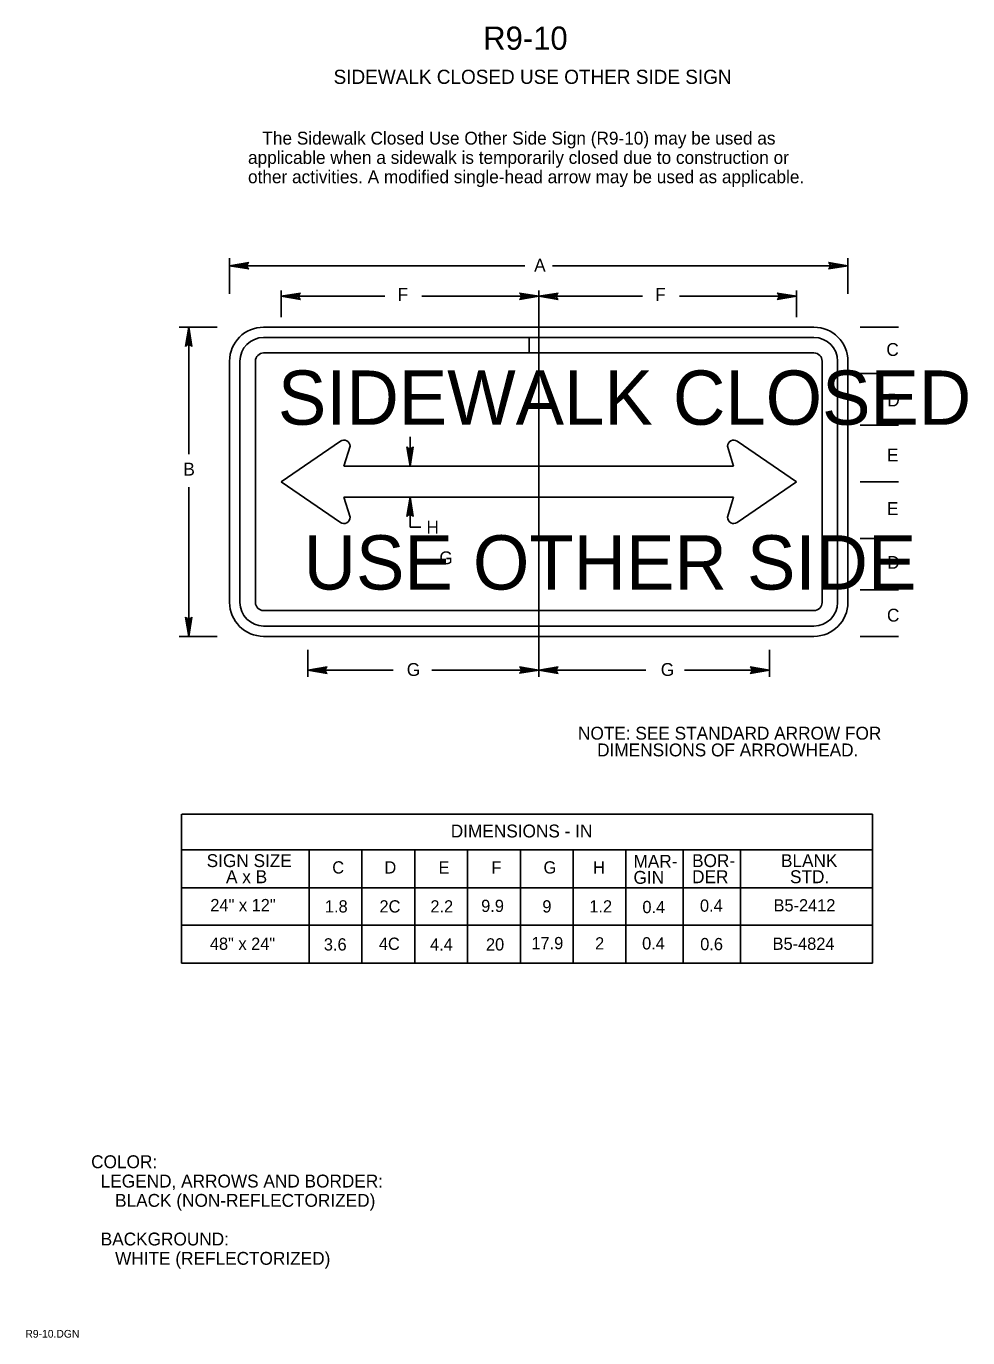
# Model space of a CAD drawing. Extents: x 0.013 to 0.195, y 0.005 to 0.259.
import ezdxf

# ---------------------------------------------------------------- set-up
doc = ezdxf.new("R2010")
doc.units = 0
for name, color, linetype in [('1', 7, 'Continuous'), ('2', 7, 'Continuous'), ('3', 7, 'Continuous')]:
    doc.layers.add(name, color=color, linetype=linetype)

# ---------------------------------------------------------------- blocks, each defined once
blk = doc.blocks.new('RARROW')
at = {"layer": '3'}
for p, q in [((-2.156, 0.28500000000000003), (-2.2665, 0.384625)), ((-2.2665, 0.384625), (0, 0)), ((0, 0), (-2.2665, -0.379125)), ((-2.156, 0.28500000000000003), (-2.075625, 0.12075)), ((0, 0), (-2.156, 0.28500000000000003)), ((-2.14975, -0.2705), (0, 0)), ((-2.075625, 0.12075), (0, 0)), ((0, 0), (-2.074, -0.108)), ((-2.2665, -0.379125), (-2.14975, -0.2705)), ((-2.074, -0.108), (-2.14975, -0.2705))]:
    blk.add_line(p, q, dxfattribs=at)

msp = doc.modelspace()

# ---------------------------------------------------------------- linework, layer by layer
at = {"layer": '1'}
for p, q in [((0.06199842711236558, 0.20792631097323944), (0.06199842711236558, 0.20273818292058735)), ((0.11199842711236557, 0.20792631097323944), (0.11199842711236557, 0.20273818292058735)), ((0.16199842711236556, 0.20792631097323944), (0.16199842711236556, 0.20273818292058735)), ((0.11199842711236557, 0.20504784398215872), (0.11199842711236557, 0.1329625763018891)), ((0.04960895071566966, 0.20079298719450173), (0.04220895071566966, 0.20079298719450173)), ((0.05859842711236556, 0.19879298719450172), (0.11011711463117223, 0.19879298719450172)), ((0.11011711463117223, 0.19879298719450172), (0.11011711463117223, 0.19579298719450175)), ((0.11011711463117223, 0.19579298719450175), (0.11011711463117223, 0.19879298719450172)), ((0.11011711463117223, 0.19879298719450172), (0.1653984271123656, 0.19879298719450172)), ((0.17438790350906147, 0.20079298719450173), (0.1817879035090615, 0.20079298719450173)), ((0.05399842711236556, 0.1473929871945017), (0.05399842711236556, 0.1941929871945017)), ((0.05699842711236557, 0.1941929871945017), (0.05699842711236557, 0.1473929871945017)), ((0.11011711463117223, 0.19579298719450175), (0.05859842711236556, 0.19579298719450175)), ((0.1653984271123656, 0.19579298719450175), (0.11011711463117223, 0.19579298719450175)), ((0.16699842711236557, 0.1473929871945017), (0.16699842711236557, 0.1941929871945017)), ((0.16999842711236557, 0.1941929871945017), (0.16999842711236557, 0.1473929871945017)), ((0.17438790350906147, 0.19179298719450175), (0.1817879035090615, 0.19179298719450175)), ((0.17438790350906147, 0.18179298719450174), (0.1817879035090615, 0.18179298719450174)), ((0.07349961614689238, 0.17868254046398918), (0.06199842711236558, 0.17079298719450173)), ((0.16199842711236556, 0.1707929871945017), (0.15049723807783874, 0.17868254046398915)), ((0.07417451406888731, 0.17379298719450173), (0.07537842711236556, 0.17769298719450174)), ((0.14861842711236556, 0.17769298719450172), (0.14982234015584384, 0.1737929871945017)), ((0.1498223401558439, 0.17379298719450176), (0.07417451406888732, 0.17379298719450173)), ((0.06199842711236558, 0.17079298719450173), (0.07349961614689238, 0.16290343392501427)), ((0.15049723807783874, 0.16290343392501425), (0.16199842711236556, 0.1707929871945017)), ((0.17438790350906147, 0.17079298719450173), (0.1817879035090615, 0.17079298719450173)), ((0.07537842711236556, 0.16389298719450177), (0.07417451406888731, 0.16779298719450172)), ((0.07417451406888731, 0.16779298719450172), (0.1498223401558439, 0.16779298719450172)), ((0.14982234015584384, 0.1677929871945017), (0.14861842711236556, 0.16389298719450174)), ((0.0890998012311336, 0.1619828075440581), (0.08701613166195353, 0.1619828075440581)), ((0.17438790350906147, 0.15979298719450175), (0.1817879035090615, 0.15979298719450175)), ((0.17438790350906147, 0.14979298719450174), (0.1817879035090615, 0.14979298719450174)), ((0.05859842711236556, 0.14579298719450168), (0.1653984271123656, 0.14579298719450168)), ((0.1653984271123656, 0.14279298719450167), (0.05859842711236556, 0.14279298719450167)), ((0.04960895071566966, 0.14079298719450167), (0.04220895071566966, 0.14079298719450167)), ((0.17438790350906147, 0.14079298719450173), (0.1817879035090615, 0.14079298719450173)), ((0.06719842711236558, 0.1329625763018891), (0.06719842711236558, 0.1381507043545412)), ((0.11199842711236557, 0.1329625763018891), (0.11199842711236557, 0.1381507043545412)), ((0.15679842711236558, 0.1329625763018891), (0.15679842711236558, 0.1381507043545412))]:
    msp.add_line(p, q, dxfattribs=at)
for centre, radius, start, end in [((0.05859842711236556, 0.1941929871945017), 0.006600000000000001, 90, 180), ((0.05859842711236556, 0.1941929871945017), 0.004600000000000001, 90, 180), ((0.1653984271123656, 0.1941929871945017), 0.006600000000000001, 0, 90), ((0.1653984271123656, 0.1941929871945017), 0.004600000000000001, 0, 90), ((0.05859842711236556, 0.1941929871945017), 0.0016, 90, 180), ((0.1653984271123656, 0.1941929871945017), 0.0016, 0, 90), ((0.07417842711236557, 0.17769298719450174), 0.0012000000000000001, 0, 124.4492335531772), ((0.1498184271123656, 0.17769298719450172), 0.0012000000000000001, 55.550766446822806, 180), ((0.07417842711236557, 0.16389298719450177), 0.0012000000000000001, 235.55076644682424, 0), ((0.1498184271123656, 0.16389298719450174), 0.0012000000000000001, 180, 304.44923355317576), ((0.05859842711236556, 0.1473929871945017), 0.006600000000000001, 180, 270), ((0.05859842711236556, 0.1473929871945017), 0.004600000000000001, 180, 270), ((0.05859842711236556, 0.1473929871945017), 0.0016, 180, 270), ((0.1653984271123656, 0.1473929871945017), 0.006600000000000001, 270, 0), ((0.1653984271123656, 0.1473929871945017), 0.0016, 270, 0), ((0.1653984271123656, 0.1473929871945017), 0.004600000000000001, 270, 0)]:
    msp.add_arc(centre, radius, start, end, dxfattribs=at)
at = {"layer": '3'}
for p, q in [((0.05199842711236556, 0.2072463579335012), (0.05199842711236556, 0.21415649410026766)), ((0.17199842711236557, 0.2072463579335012), (0.17199842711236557, 0.21415649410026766)), ((0.10927705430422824, 0.21271933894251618), (0.05199842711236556, 0.21271933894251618)), ((0.11463473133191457, 0.21271933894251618), (0.17199842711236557, 0.21271933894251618)), ((0.08215111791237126, 0.2067858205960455), (0.06199842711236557, 0.2067858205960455)), ((0.11199842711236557, 0.2067858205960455), (0.08933127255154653, 0.2067858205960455)), ((0.13215111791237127, 0.2067858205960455), (0.11199842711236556, 0.2067858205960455)), ((0.16199842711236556, 0.2067858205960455), (0.13933127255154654, 0.2067858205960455)), ((0.044054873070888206, 0.17614255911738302), (0.044054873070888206, 0.20079298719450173)), ((0.05859842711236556, 0.20079298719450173), (0.1653984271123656, 0.20079298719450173)), ((0.05199842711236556, 0.1473929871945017), (0.05199842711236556, 0.1941929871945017)), ((0.17199842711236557, 0.1473929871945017), (0.17199842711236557, 0.1941929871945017)), ((0.08701613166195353, 0.17379298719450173), (0.08701613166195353, 0.1794839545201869)), ((0.044054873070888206, 0.14079298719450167), (0.044054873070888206, 0.1697685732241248)), ((0.08701613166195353, 0.1619828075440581), (0.08701613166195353, 0.16779298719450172)), ((0.05859842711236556, 0.14079298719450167), (0.1653984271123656, 0.14079298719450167)), ((0.08373753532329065, 0.13424514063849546), (0.06719842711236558, 0.13424514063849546)), ((0.11199842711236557, 0.13424514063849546), (0.09122230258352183, 0.13424514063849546)), ((0.11199842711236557, 0.13424514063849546), (0.13277455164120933, 0.13424514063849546)), ((0.1402593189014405, 0.13424514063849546), (0.15679842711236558, 0.13424514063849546)), ((0.042671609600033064, 0.10626767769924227), (0.042671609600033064, 0.07739267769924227)), ((0.04271319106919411, 0.10626480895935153), (0.1767966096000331, 0.10626480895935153)), ((0.1767966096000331, 0.10626767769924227), (0.1767966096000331, 0.07739554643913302)), ((0.1767966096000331, 0.09939267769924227), (0.042671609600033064, 0.09939267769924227)), ((0.06746319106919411, 0.09938980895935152), (0.06746319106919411, 0.07739267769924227)), ((0.07767160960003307, 0.09939267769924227), (0.07767160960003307, 0.07739267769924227)), ((0.08792160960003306, 0.09939267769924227), (0.08792160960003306, 0.07739267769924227)), ((0.09817160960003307, 0.09939267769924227), (0.09817160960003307, 0.07739267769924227)), ((0.10842160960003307, 0.09939267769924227), (0.10842160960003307, 0.07739267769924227)), ((0.11867160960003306, 0.09939267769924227), (0.11867160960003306, 0.07739267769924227)), ((0.12888002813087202, 0.09939554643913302), (0.12888002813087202, 0.07739554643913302)), ((0.1400466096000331, 0.09939267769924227), (0.1400466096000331, 0.07739554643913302)), ((0.1511716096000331, 0.09939267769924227), (0.1511716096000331, 0.07739554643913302)), ((0.1767966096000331, 0.09201767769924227), (0.042671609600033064, 0.09201767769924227)), ((0.1767966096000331, 0.08476767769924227), (0.042671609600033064, 0.08476767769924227)), ((0.1767966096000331, 0.07739267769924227), (0.042671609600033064, 0.07739267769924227))]:
    msp.add_line(p, q, dxfattribs=at)

# ---------------------------------------------------------------- block references
at = {"layer": '3', "xscale": 0.001654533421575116}
for p, yscale, rotation in [((0.05199842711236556, 0.21271933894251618), 0.0016366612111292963, 180), ((0.06199842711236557, 0.2067858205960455), 0.0016366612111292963, 180), ((0.11199842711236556, 0.2067858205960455), 0.0016366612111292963, 180), ((0.044054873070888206, 0.20079298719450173), 0.0016366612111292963, 89.99999999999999), ((0.08701613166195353, 0.17379298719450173), -0.0016366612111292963, -89.99999999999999), ((0.08701613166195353, 0.16779298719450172), 0.0016366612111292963, 89.99999999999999), ((0.044054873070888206, 0.14079298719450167), -0.0016366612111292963, -89.99999999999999), ((0.06719842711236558, 0.13424514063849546), 0.0016366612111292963, 180), ((0.11199842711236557, 0.13424514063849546), 0.0016366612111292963, 180)]:
    msp.add_blockref('RARROW', p, dxfattribs=dict(at, yscale=yscale, rotation=rotation))
for p, yscale in [((0.17199842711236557, 0.21271933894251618), 0.0016366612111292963), ((0.11199842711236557, 0.2067858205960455), 0.0016366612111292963), ((0.16199842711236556, 0.2067858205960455), 0.0016366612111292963), ((0.11199842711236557, 0.13424514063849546), 0.0016366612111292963), ((0.15679842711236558, 0.13424514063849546), -0.0016366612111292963)]:
    msp.add_blockref('RARROW', p, dxfattribs=dict(at, yscale=yscale))

# ---------------------------------------------------------------- texts
at = {"layer": '1'}
for s, height, p in [('R9-10', 0.0045000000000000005, (0.10121931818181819, 0.254625)), ('SIDEWALK CLOSED USE OTHER SIDE SIGN', 0.00275025, (0.07217794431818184, 0.248)), ('SIDEWALK CLOSED', 0.010528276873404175, (0.06136717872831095, 0.18185914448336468)), ('COLOR:', 0.0024997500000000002, (0.025125, 0.03758760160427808)), ('  LEGEND, ARROWS AND BORDER:', 0.0024997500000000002, (0.025125, 0.03383785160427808)), ('     BLACK (NON-REFLECTORIZED) ', 0.0024997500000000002, (0.025125, 0.03008810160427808)), ('  BACKGROUND:', 0.0024997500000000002, (0.025125, 0.022588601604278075)), ('     WHITE (REFLECTORIZED)          ', 0.0024997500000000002, (0.025125, 0.018838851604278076)), ('R9-10.DGN', 0.0015, (0.012361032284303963, 0.004699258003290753))]:
    msp.add_text(s, height=height, dxfattribs=at).set_placement(p)
msp.add_text('USE OTHER SIDE', height=0.010528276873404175, rotation=360, dxfattribs=at).set_placement((0.06636539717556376, 0.14987753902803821))
at = {"layer": '2'}
for s, p in [('   The Sidewalk Closed Use Other Side Sign (R9-10) may be used as', (0.05556792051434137, 0.23622376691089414)), ('applicable when a sidewalk is temporarily closed due to construction or', (0.05556792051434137, 0.23247401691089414)), ('other activities. A modified single-head arrow may be used as applicable.', (0.05556792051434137, 0.22872426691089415))]:
    msp.add_text(s, height=0.0024997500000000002, dxfattribs=at).set_placement(p)
at = {"layer": '3'}
for s, height, p in [('A', 0.0024997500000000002, (0.11110305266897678, 0.21158424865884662)), ('F', 0.0024997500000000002, (0.08459336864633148, 0.2058954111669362)), ('F', 0.0024997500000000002, (0.13459336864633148, 0.2058954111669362)), ('B', 0.0024997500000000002, (0.043023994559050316, 0.17199112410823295)), ('H', 0.0024997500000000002, (0.09019816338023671, 0.1607204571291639)), ('G', 0.0024997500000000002, (0.09269947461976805, 0.15478084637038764)), ('G', 0.0024997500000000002, (0.13568022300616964, 0.13310663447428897)), ('NOTE: SEE STANDARD ARROW FOR', 0.0024997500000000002, (0.11960854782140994, 0.12075197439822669)), ('    DIMENSIONS OF ARROWHEAD.', 0.0024997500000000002, (0.11960854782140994, 0.11750222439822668)), ('SIGN SIZE', 0.0024997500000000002, (0.04754660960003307, 0.09601767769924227)), ('C', 0.0023752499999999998, (0.07192160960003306, 0.09476767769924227)), ('D', 0.0023752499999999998, (0.08204660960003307, 0.09476767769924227)), ('E', 0.0023752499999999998, (0.09254660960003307, 0.09476767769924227)), ('F', 0.0023752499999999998, (0.10279660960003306, 0.09476767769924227)), ('G', 0.0023752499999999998, (0.11292160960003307, 0.09476767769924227)), ('MAR-', 0.0024997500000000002, (0.13038002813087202, 0.09589554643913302)), ('BOR-', 0.0024997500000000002, (0.14175502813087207, 0.09602054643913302)), ('BLANK', 0.0024997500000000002, (0.15900502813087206, 0.09602054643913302)), ('A x B', 0.0024997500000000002, (0.051296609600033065, 0.09289267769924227)), ('GIN', 0.0024997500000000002, (0.13038002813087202, 0.09277054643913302)), ('DER', 0.0024997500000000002, (0.14175502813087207, 0.09289554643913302)), ('STD.', 0.0024997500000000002, (0.16075502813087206, 0.09289554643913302)), ('24" x 12"', 0.0023752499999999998, (0.04825795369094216, 0.08745505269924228)), ('1.8', 0.0023752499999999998, (0.07049309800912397, 0.08720505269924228)), ('2C', 0.0023752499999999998, (0.08108618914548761, 0.08720505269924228)), ('2.2', 0.0023752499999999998, (0.09096658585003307, 0.08720505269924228)), ('9.9', 0.0023752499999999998, (0.10082620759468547, 0.08730719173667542)), ('9', 0.0023752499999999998, (0.11269727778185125, 0.08720505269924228)), ('0.4', 0.0023752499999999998, (0.1321120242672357, 0.08708292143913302)), ('0.4', 0.0023752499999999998, (0.14328414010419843, 0.0873580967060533)), ('B5-2412', 0.0023752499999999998, (0.15756099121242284, 0.08741594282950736)), ('48" x 24"', 0.0023752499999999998, (0.04816702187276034, 0.07995505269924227)), ('3.6', 0.0023752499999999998, (0.07029012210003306, 0.07983005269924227)), ('4C', 0.0023752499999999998, (0.08096118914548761, 0.07995505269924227)), ('4.4', 0.0023752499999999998, (0.0909036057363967, 0.07983005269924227)), ('20', 0.0023752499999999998, (0.10175293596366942, 0.07983005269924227)), ('17.9', 0.0023752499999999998, (0.1105739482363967, 0.08008005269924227)), ('2', 0.0023752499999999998, (0.12292662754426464, 0.08002501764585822)), ('0.4', 0.0023752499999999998, (0.13205698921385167, 0.08003843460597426)), ('0.6', 0.0023752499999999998, (0.1433336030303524, 0.079888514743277)), ('B5-4824', 0.0023752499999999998, (0.15738421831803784, 0.07995979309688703))]:
    msp.add_text(s, height=height, dxfattribs=at).set_placement(p)
for s, height, p in [('C', 0.0024997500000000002, (0.17945763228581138, 0.19520972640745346)), ('D', 0.0024997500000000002, (0.1796424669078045, 0.1854142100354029)), ('E', 0.0024997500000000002, (0.1795821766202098, 0.1747356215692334)), ('E', 0.0024997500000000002, (0.1795821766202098, 0.16434146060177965)), ('D', 0.0024997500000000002, (0.17961254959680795, 0.15389673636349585)), ('C', 0.0024997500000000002, (0.17957730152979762, 0.14365327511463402)), ('G', 0.0024997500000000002, (0.08638121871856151, 0.13310663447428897)), ('DIMENSIONS - IN', 0.0024997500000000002, (0.09492267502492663, 0.10176767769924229)), ('H', 0.0023752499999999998, (0.12254120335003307, 0.09476767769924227)), ('1.2', 0.0023752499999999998, (0.12180751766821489, 0.08720505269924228))]:
    msp.add_text(s, height=height, rotation=360, dxfattribs=at).set_placement(p)

doc.saveas('drawing.dxf')
